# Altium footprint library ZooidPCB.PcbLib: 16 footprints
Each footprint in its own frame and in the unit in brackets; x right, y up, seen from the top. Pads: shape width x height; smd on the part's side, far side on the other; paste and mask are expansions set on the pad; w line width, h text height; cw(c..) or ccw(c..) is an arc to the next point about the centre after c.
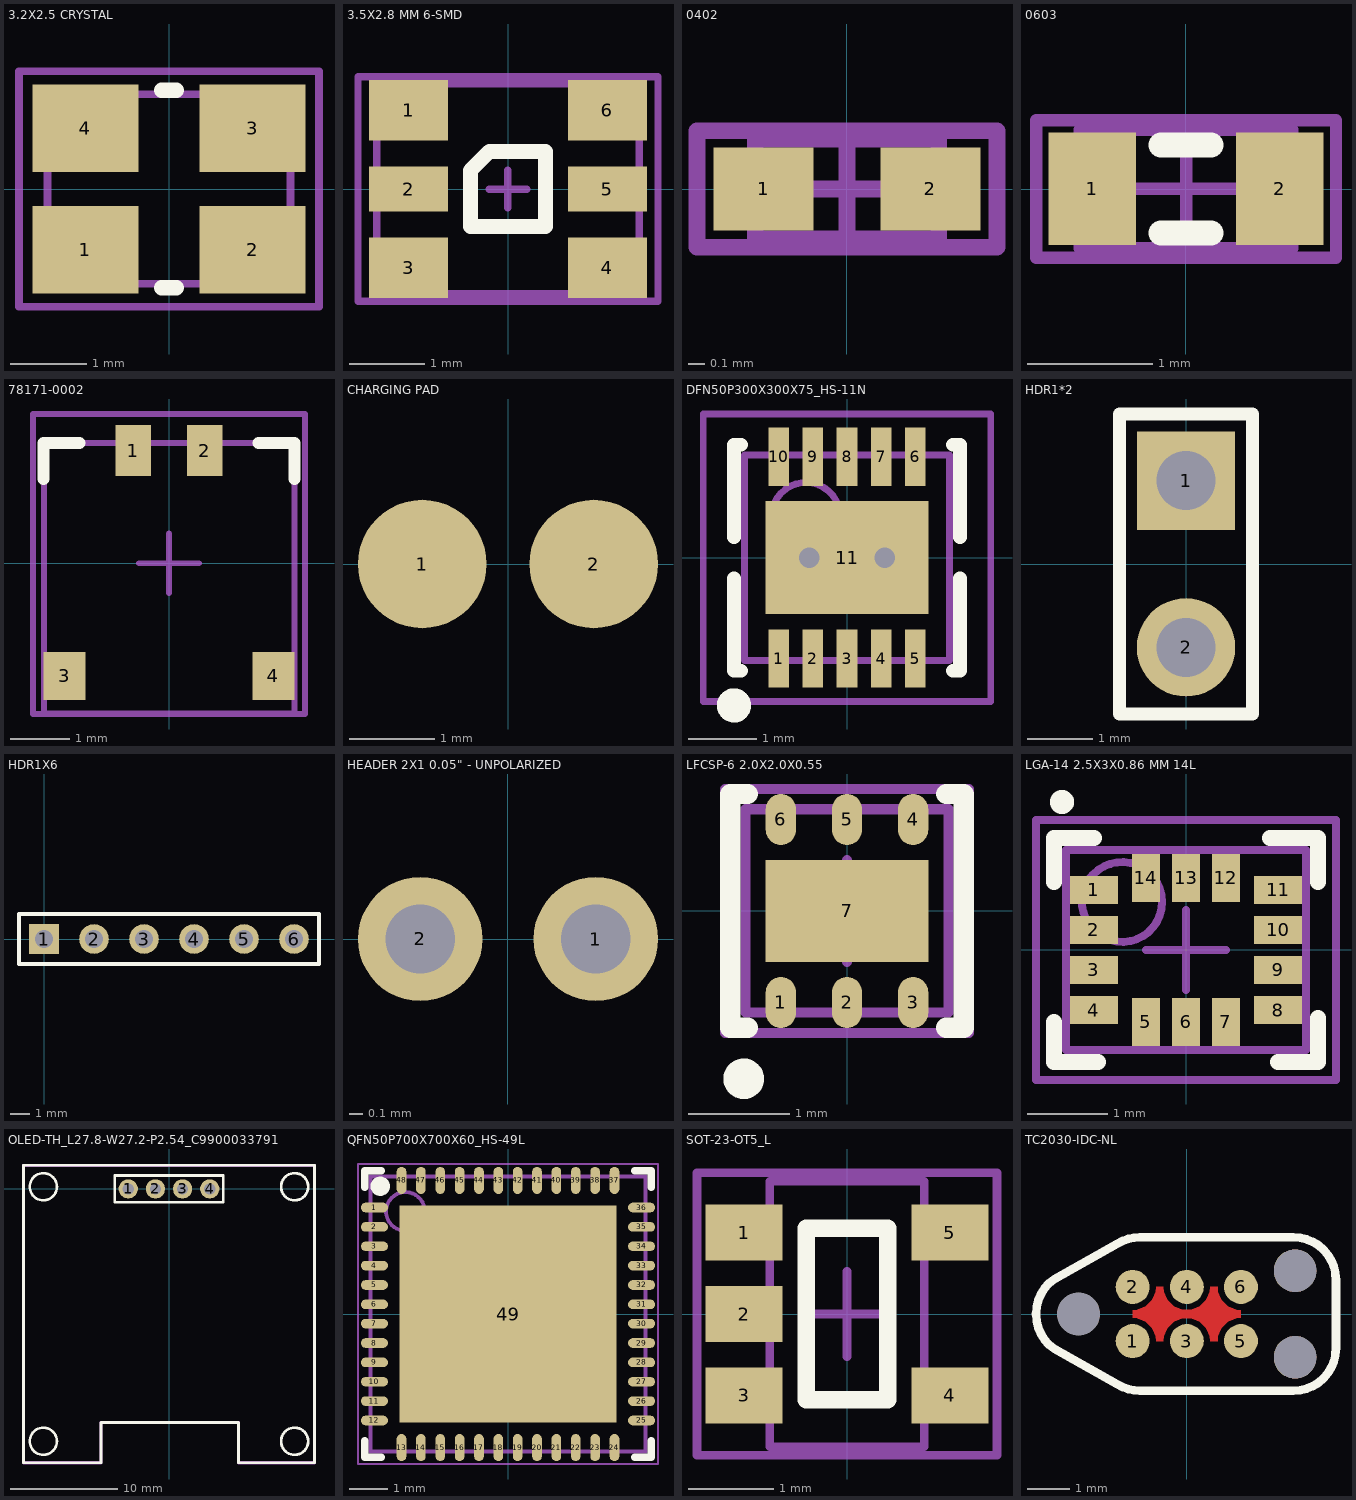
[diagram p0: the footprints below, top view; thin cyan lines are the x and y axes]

## 3.2X2.5 CRYSTAL [mm]
height 0.8
pads (4):
  rect 1.4x1.15 smd: 1(-1.1,-0.8) 2(1.1,-0.8) 3(1.1,0.8) 4(-1.1,0.8)
Top Overlay:
  lines w0.2: -0.1,-1.3 0.1,-1.3 ; -0.1,1.3 0.1,1.3
Mechanical 1:
  lines w0.1: -1.6,-1.25 -1.6,1.25 1.6,1.25 1.6,-1.25 -1.6,-1.25
Mechanical 15:
  lines w0.1: -1.975,-1.55 1.975,-1.55 1.975,1.55 -1.975,1.55 -1.975,-1.55
3D body: height 0.8, standoff 0, extent -1.6,-1.25 1.6,1.25

## 3.5X2.8 MM 6-SMD [mm] "3.5 x 2.8 mm 6-SMD Flat Leads"
height 0.6
pads (6):
  rect 1.05x0.8 smd: 1(-1.325,1.05) 3(-1.325,-1.05) 4(1.325,-1.05) 6(1.325,1.05)
  rect 1.05x0.6 smd: 2(-1.325,0) 5(1.325,0)
Top Overlay:
  lines w0.2: -0.5,-0.5 -0.5,0.25 -0.25,0.5 0.5,0.5 0.5,-0.5 -0.5,-0.5
Mechanical 13:
  lines w0.1: -1.75,-1.4 1.75,-1.4 1.75,1.4 -1.75,1.4 -1.75,-1.4
Mechanical 15:
  lines w0.1: -0.25,0 0.25,0 ; 0,-0.25 0,0.25 ; -2,-1.5 -2,1.5 2,1.5 2,-1.5 -2,-1.5
3D body "27979.stp": height 0.6, standoff 0, extent -1.75,-1.4 1.75,1.4

## 0402 [mm] "Chip Body 1.0 x 0.5 mm (LxW typ)"
height 0.55
pads (2):
  rect 0.6x0.5 smd: 1(-0.5,0) 2(0.5,0)
Mechanical 13:
  lines w0.1: -0.55,-0.3 0.55,-0.3 0.55,0.3 -0.55,0.3 -0.55,-0.3
Mechanical 15:
  lines w0.1: -0.3,0 0.3,0 ; 0,-0.3 0,0.3 ; -0.9,-0.35 0.9,-0.35 0.9,0.35 -0.9,0.35 -0.9,-0.35
3D body: height 0.55, standoff 0, extent -0.55,-0.3 0.55,0.3

## 0603 [mm] "Chip Body 1.6 x 0.8 mm (LxW typ)"
height 0.87
pads (2):
  rect 0.7x0.9 smd: 1(-0.75,0) 2(0.75,0)
Top Overlay:
  lines w0.2: -0.2,-0.35 0.2,-0.35 ; -0.2,0.35 0.2,0.35
Mechanical 13:
  lines w0.1: -0.85,-0.475 -0.85,0.475 0.85,0.475 0.85,-0.475 -0.85,-0.475
Mechanical 15:
  lines w0.1: -0.475,0 0.475,0 ; 0,-0.475 0,0.475 ; -1.2,-0.55 -1.2,0.55 1.2,0.55 1.2,-0.55 -1.2,-0.55
3D body: height 0.9, standoff 0, extent -0.85,-0.475 0.85,0.475

## 78171-0002 [mm]
height 1.55
pads (4):
  rect 0.6x0.85 smd: 1(-0.6,1.888) 2(0.6,1.888)
  rect 0.7x0.8 smd: 3(-1.75,-1.887) 4(1.75,-1.887)
Top Overlay:
  lines w0.2: -2.1,1.413 -2.1,2.013 -1.5,2.013 ; 1.5,2.013 2.1,2.013 2.1,1.413
Mechanical 1:
  lines w0.1: -2.095,-2.512 2.1,-2.512 2.1,2.013 -2.095,2.013 -2.095,-2.512
Mechanical 15:
  lines w0.1: -0.5,0 0.5,0 ; 0,-0.5 0,0.5 ; -2.275,-2.525 -2.275,2.5 2.275,2.5 2.275,-2.525 -2.275,-2.525
3D body "781710002.stp": height 1.45, standoff 0, extent -2.1,-2.512 2.1,2.018

## CHARGING PAD [mm]
pads (2):
  round 1.5 smd paste-5: 1(-1,0) 2(1,0)
3D body: height 0, standoff 0, extent -1.744,-0.749 -0.25,0.749
3D body: height 0, standoff 0, extent 0.252,-0.749 1.746,0.749

## DFN50P300X300X75_HS-11N [mm]
pads (11):
  rect 0.3x0.85 smd: 1(-1,-1.475) 2(-0.5,-1.475) 3(0,-1.475) 4(0.5,-1.475) 5(1,-1.475) 6(1,1.475) 7(0.5,1.475) 8(0,1.475) 9(-0.5,1.475) 10(-1,1.475)
  rect 2.38x1.65 smd: 11(0,0)
via 0.55,0 diameter 0.6 hole 0.3
via -0.55,0 diameter 0.6 hole 0.3
Top Overlay:
  circle w0.25: c-1.651,-2.159 r0.125
  lines w0.2: -1.65,-0.3 -1.65,-1.65 -1.55,-1.65 ; -1.65,0.3 -1.65,1.65 -1.55,1.65 ; 1.55,-1.65 1.65,-1.65 1.65,-0.3 ; 1.55,1.65 1.65,1.65 1.65,0.3
Mechanical 13:
  circle w0.1: c-0.6,0.6 r0.5
  lines w0.1: -1.5,-1.5 1.5,-1.5 1.5,1.5 -1.5,1.5 -1.5,-1.5
Mechanical 15:
  lines w0.1: -0.5,0 0.5,0 ; 0,-0.5 0,0.5 ; -2.1,-2.1 2.1,-2.1 2.1,2.1 -2.1,2.1 -2.1,-2.1
3D body: height 0.75, standoff 0, extent -1.5,-1.5 1.5,1.5

## HDR1*2 [mm]
pads (2):
  rect 1.5x1.5 hole 0.9: 1(0,1.27)
  round 1.5 hole 0.9: 2(0,-1.27)
Top Overlay:
  lines w0.2: -1.016,-2.286 -1.016,2.286 1.016,2.286 1.016,-2.286 -1.016,-2.286

## HDR1X6 [mm] "Connector; Header; 6 Position"
pads (6):
  rect 1.5x1.5 hole 0.9: 1(0,0)
  round 1.5 hole 0.9: 2(2.54,0) 3(5.08,0) 4(7.62,0) 5(10.16,0) 6(12.7,0)
Top Overlay:
  lines w0.2: -1.27,-1.27 -1.27,1.27 13.97,1.27 13.97,-1.27 -1.27,-1.27

## HEADER 2X1 0.05" - UNPOLARIZED [mm]
pads (2):
  round 0.9 hole 0.5: 1(0.635,0) 2(-0.635,0)
3D body: height 0.01, standoff 0, extent -1.25,-0.6 1.25,0.6

## LFCSP-6 2.0X2.0X0.55 [mm] ". 6-Lead Lead Frame Chip Scale Package [LFCSP_UD]  2.00 mm?2.00 mm Body, Ultra Thin, Dual Lead  (CP-6-3)"
height 0.55
pads (7):
  oval 0.3x0.5 smd: 1(-0.65,-0.9) 2(0,-0.9) 3(0.65,-0.9) 4(0.65,0.9) 5(0,0.9) 6(-0.65,0.9)
  rect 1.6x1 smd: 7(0,0)
Top Overlay:
  circle w0.2: c-1.016,-1.651 r0.1
  lines w0.2: -1.15,-1.15 -0.975,-1.15 ; -1.15,-1.125 -1.15,1.15 -0.975,1.15 ; 0.975,-1.15 1.15,-1.15 1.15,1.125 ; 0.975,1.15 1.15,1.15
Mechanical 13:
  lines w0.1: -1,-1 1,-1 1,1 -1,1 -1,-1
Mechanical 15:
  lines w0.1: -0.5,0 0.5,0 ; 0,-0.5 0,0.5 ; -1.2,-1.2 1.2,-1.2 1.2,1.2 -1.2,1.2 -1.2,-1.2
3D body: height 0.6, standoff 0.05, extent -1,-1 1,1

## LGA-14 2.5X3X0.86 MM 14L [mm] "LGA, 14-Leads, Body 3.00x2.50mm, Pitch 0.50mm, IPC High Density"
height 0.86
pads (14):
  rect 0.6x0.35 smd: 1(-1.15,0.75) 2(-1.15,0.25) 3(-1.15,-0.25) 4(-1.15,-0.75) 8(1.15,-0.75) 9(1.15,-0.25) 10(1.15,0.25) 11(1.15,0.75)
  rect 0.35x0.6 smd: 5(-0.5,-0.9) 6(0,-0.9) 7(0.5,-0.9) 12(0.5,0.9) 13(0,0.9) 14(-0.5,0.9)
Top Overlay:
  circle w0.2: c-1.55,1.85 r0.05
  lines w0.2: -1.65,-0.9 -1.65,-1.4 -1.1,-1.4 ; -1.65,0.85 -1.65,1.4 -1.15,1.4 ; 1.05,1.4 1.65,1.4 1.65,0.85 ; 1.15,-1.4 1.65,-1.4 1.65,-0.85
Mechanical 13:
  circle w0.1: c-0.8,0.6 r0.5
  lines w0.1: -1.5,-1.25 1.5,-1.25 1.5,1.25 -1.5,1.25 -1.5,-1.25
Mechanical 15:
  lines w0.1: -0.5,0 0.5,0 ; 0,-0.5 0,0.5 ; -1.875,-1.625 -1.875,1.625 1.875,1.625 1.875,-1.625 -1.875,-1.625
3D body: height 0.86, standoff 0.13, extent -1.5,-1.25 1.5,1.25

## OLED-TH_L27.8-W27.2-P2.54_C9900033791 [mm]
pads (4):
  round 1.8 hole 1.05 paste-2539.97 mask+0.05: 1(-3.81,0) 2(-1.27,0) 3(1.27,0) 4(3.81,0)
Top Overlay:
  circle w0.254: c-11.75,0.2 r1.27
  circle w0.254: c11.75,0.2 r1.27
  circle w0.254: c11.75,-23.6 r1.27
  circle w0.254: c-11.75,-23.6 r1.27
  lines w0.254: -13.599,-25.601 -6.35,-25.601 -6.35,-21.849 6.5,-21.849 6.5,-25.601 13.599,-25.601 13.599,2.2 -13.599,2.2 -13.599,-25.601 ; -5.08,-1.25 -5.08,1.25 5.08,1.25 5.08,-1.25 -5.08,-1.25
Mechanical 6:
  region: 6.5,-25.727 6.475,-25.727 6.428,-25.708 6.392,-25.672 6.373,-25.625 6.373,-25.6 6.373,-21.977 -6.223,-21.977 -6.223,-25.6 -6.223,-25.625 -6.242,-25.672 -6.278,-25.708 -6.325,-25.727 -6.35,-25.727 -13.6,-25.727 -13.625,-25.727 -13.672,-25.708 -13.708,-25.672 -13.727,-25.625 -13.727,-25.6 -13.727,2.2 -13.727,2.225 -13.708,2.272 -13.672,2.308 -13.625,2.327 -13.6,2.327 -13.575,2.327 -13.528,2.308 -13.492,2.272 -13.473,2.225 -13.473,2.2 -13.473,-25.473 -6.477,-25.473 -6.477,-21.85 -6.477,-21.825 -6.458,-21.778 -6.422,-21.742 -6.375,-21.723 -6.35,-21.723 6.5,-21.723 6.525,-21.723 6.572,-21.742 6.608,-21.778 6.627,-21.825 6.627,-21.85 6.627,-25.473 13.473,-25.473 13.473,2.2 13.473,2.225 13.492,2.272 13.528,2.308 13.575,2.327 13.6,2.327 13.625,2.327 13.672,2.308 13.708,2.272 13.727,2.225 13.727,2.2 13.727,-25.6 13.727,-25.625 13.708,-25.672 13.672,-25.708 13.625,-25.727 13.6,-25.727
  region: 13.6,2.073 -13.6,2.073 -13.653,2.073 -13.727,2.147 -13.727,2.253 -13.653,2.327 -13.6,2.327 13.6,2.327 13.653,2.327 13.727,2.253 13.727,2.147 13.653,2.073 13.6,2.073
Mechanical 15:
  region: -13.539,-25.601 -13.539,-25.576 -13.574,-25.541 -13.624,-25.541 -13.659,-25.576 -13.659,-25.601 -13.659,-25.626 -13.624,-25.661 -13.574,-25.661 -13.539,-25.626 -13.539,-25.601
  region: 3.49,0.32 4.13,0.32 4.13,-0.32 3.49,-0.32
  region: 0.95,0.32 1.59,0.32 1.59,-0.32 0.95,-0.32
  region: -1.59,0.32 -0.95,0.32 -0.95,-0.32 -1.59,-0.32
  region: -4.13,0.32 -3.49,0.32 -3.49,-0.32 -4.13,-0.32
  lines w0.051: -13.599,-25.601 -6.35,-25.601 -6.35,-21.849 6.5,-21.849 6.5,-25.601 13.599,-25.601 13.599,2.2 -13.599,2.2 -13.599,-25.601

## QFN50P700X700X60_HS-49L [mm] "QFN, 48-Leads, Body 7,00x7,00mm, Pitch 0,50mm, Thermal Pad 5,60x5,60mm, IPC High Density"
height 0.6
pads (49):
  oval 0.7x0.25 smd: 1(-3.45,2.75) 2(-3.45,2.25) 3(-3.45,1.75) 4(-3.45,1.25) 5(-3.45,0.75) 6(-3.45,0.25) 7(-3.45,-0.25) 8(-3.45,-0.75) 9(-3.45,-1.25) 10(-3.45,-1.75) 11(-3.45,-2.25) 12(-3.45,-2.75) 25(3.45,-2.75) 26(3.45,-2.25) 27(3.45,-1.75) 28(3.45,-1.25) 29(3.45,-0.75) 30(3.45,-0.25) 31(3.45,0.25) 32(3.45,0.75) 33(3.45,1.25) 34(3.45,1.75) 35(3.45,2.25) 36(3.45,2.75)
  oval 0.25x0.7 smd: 13(-2.75,-3.45) 14(-2.25,-3.45) 15(-1.75,-3.45) 16(-1.25,-3.45) 17(-0.75,-3.45) 18(-0.25,-3.45) 19(0.25,-3.45) 20(0.75,-3.45) 21(1.25,-3.45) 22(1.75,-3.45) 23(2.25,-3.45) 24(2.75,-3.45) 37(2.75,3.45) 38(2.25,3.45) 39(1.75,3.45) 40(1.25,3.45) 41(0.75,3.45) 42(0.25,3.45) 43(-0.25,3.45) 44(-0.75,3.45) 45(-1.25,3.45) 46(-1.75,3.45) 47(-2.25,3.45) 48(-2.75,3.45)
  rect 5.6x5.6 smd: 49(0,0)
Top Overlay:
  circle w0.25: c-3.3,3.3 r0.125
  lines w0.2: -3.7,-3.275 -3.7,-3.7 -3.275,-3.7 ; -3.7,3.275 -3.7,3.7 -3.275,3.7 ; 3.275,-3.7 3.7,-3.7 3.7,-3.275 ; 3.275,3.7 3.7,3.7 3.7,3.275
Mechanical 13:
  circle w0.1: c-2.65,2.65 r0.5
  lines w0.1: -3.55,-3.55 -3.55,3.55 3.55,3.55 3.55,-3.55 -3.55,-3.55
Mechanical 15:
  lines w0.05: -3.875,-3.875 -3.875,3.875 3.875,3.875 3.875,-3.875 -3.875,-3.875
  lines w0.1: -0.5,0 0.5,0 ; 0,-0.5 0,0.5
3D body: height 0.6, standoff 0.05, extent -3.55,-3.55 3.55,3.55

## SOT-23-OT5_L [mm] "SOT23, 5-Leads, Body 2.9x1.6mm, Pitch 0.95mm, Lead Span 2.7mm, IPC High Density"
height 1.45
pads (5):
  rect 0.9x0.65 smd: 1(-1.2,0.95) 2(-1.2,0) 3(-1.2,-0.95) 4(1.2,-0.95) 5(1.2,0.95)
Top Overlay:
  lines w0.2: -0.475,-1 -0.475,1 0.475,1 0.475,-1 -0.475,-1
Mechanical 13:
  lines w0.1: -0.9,-1.55 0.9,-1.55 0.9,1.55 -0.9,1.55 -0.9,-1.55
Mechanical 15:
  lines w0.1: -0.5,0 0.5,0 ; 0,-0.5 0,0.5 ; -1.75,-1.65 1.75,-1.65 1.75,1.65 -1.75,1.65 -1.75,-1.65
3D body: height 1.45, standoff 0, extent -0.9,-1.55 0.9,1.55

## TC2030-IDC-NL [mm] "TagConnector TC2030-IDC-NL"
pads (9):
  round 0.8 smd paste-1: 1(-1.27,-0.635) 2(-1.27,0.635) 3(0,-0.635) 4(0,0.635) 5(1.27,-0.635) 6(1.27,0.635)
  round 1 hole 1 unplated mask+0: ""(-2.54,0) ""(2.54,-1.016) ""(2.54,1.016)
Top Layer:
  pour cut-out: -1.27,-0.085 -1.27,0.085 -1.163,0.096 -0.964,0.178 -0.813,0.329 -0.731,0.528 -0.72,0.635 -0.55,0.635 -0.539,0.528 -0.457,0.329 -0.306,0.178 -0.107,0.096 0.107,0.096 0.306,0.178 0.457,0.329 0.539,0.528 0.55,0.635 0.72,0.635 0.731,0.528 0.813,0.329 0.964,0.178 1.163,0.096 1.27,0.085 1.27,-0.085 1.163,-0.096 0.964,-0.178 0.813,-0.329 0.731,-0.528 0.72,-0.635 0.55,-0.635 0.539,-0.528 0.457,-0.329 0.306,-0.178 0.107,-0.096 -0.107,-0.096 -0.306,-0.178 -0.457,-0.329 -0.539,-0.528 -0.55,-0.635 -0.72,-0.635 -0.731,-0.528 -0.813,-0.329 -0.964,-0.178 -1.163,-0.096
Top Overlay:
  lines w0.2: -3.111,-0.816 cw(c-2.544,0) -3.111,0.816 -1.63,1.648 cw(c-1.1,0.8) -1.1,1.8 2.5,1.8 cw(c2.5,0.8) 3.5,0.8 3.5,-0.8 cw(c2.5,-0.8) 2.5,-1.8 -1.1,-1.8 cw(c-1.1,-0.8) -1.63,-1.648 -3.111,-0.816
Mechanical 15:
  lines w0.1: -3.111,-0.816 cw(c-2.544,0) -3.111,0.816 -1.63,1.648 cw(c-1.1,0.8) -1.1,1.8 2.5,1.8 cw(c2.5,0.8) 3.5,0.8 3.5,-0.8 cw(c2.5,-0.8) 2.5,-1.8 -1.1,-1.8 cw(c-1.1,-0.8) -1.63,-1.648 -3.111,-0.816
3D body: height 0, standoff 0, extent -1.667,0.236 -0.87,1.034
3D body: height 0, standoff 0, extent -0.397,0.236 0.4,1.034
3D body: height 0, standoff 0, extent -0.4,-1.034 0.397,-0.236
3D body: height 0, standoff 0, extent -1.67,-1.034 -0.873,-0.236
3D body: height 0, standoff 0, extent 0.87,-1.034 1.667,-0.236
3D body: height 0, standoff 0, extent 0.873,0.236 1.67,1.034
